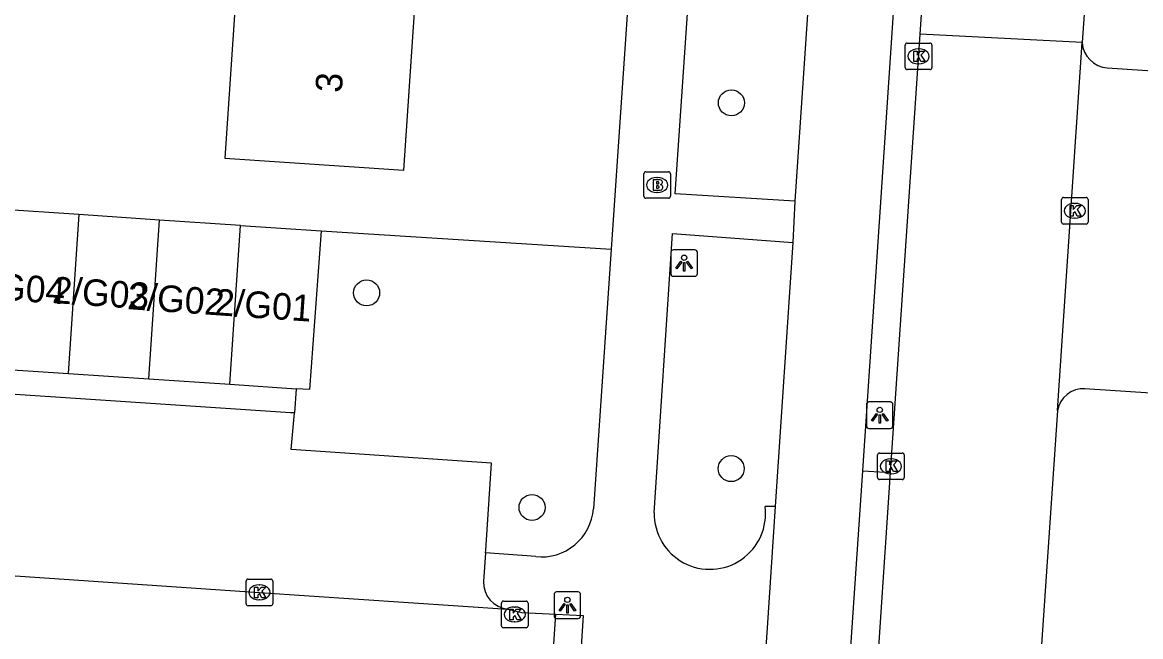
# Model space of a CAD drawing. Extents: x 161848 to 162726, y 385382 to 386521.
# Drawn here: x 161976.28 to 162018.35, y 385610.51 to 385633.63 of the extents above; entities that cross this region are included whole.
import ezdxf

# ---------------------------------------------------------------- set-up
doc = ezdxf.new("R2010")
doc.units = 0
for name, color, linetype in [('IMGEO_Boom', 7, 'Continuous'), ('IMGEO_Brandkraan', 7, 'Continuous'), ('IMGEO_Fietspad_gesloten', 7, 'Continuous'), ('IMGEO_Groenvoorziening', 7, 'Continuous'), ('IMGEO_Kolk', 7, 'Continuous'), ('IMGEO_Lichtpunt', 7, 'Continuous'), ('IMGEO_Pand', 7, 'Continuous'), ('IMGEO_Pand_nummerreeks', 7, 'Continuous'), ('IMGEO_Parkeervlak_open', 7, 'Continuous'), ('IMGEO_Rijbaan_lokaal_open', 7, 'Continuous'), ('IMGEO_Voetpad_open', 7, 'Continuous')]:
    doc.layers.add(name, color=color, linetype=linetype)

msp = doc.modelspace()

# ---------------------------------------------------------------- linework, layer by layer
at = {"layer": 'IMGEO_Boom'}
for centre in [(162002.953, 385630.598), (161989.23, 385623.445), (162002.946, 385616.832), (161995.453, 385615.371)]:
    msp.add_circle(centre, 0.489, dxfattribs=at)
at = {"layer": 'IMGEO_Brandkraan'}
for p, q in [((161999.659, 385627.081), (161999.659, 385627.933)), ((161999.734, 385628.007), (162000.586, 385628.007)), ((162000.66, 385627.933), (162000.66, 385627.081)), ((162000.147, 385627.787), (162000.172, 385627.787)), ((162000.586, 385627.007), (161999.734, 385627.007)), ((162000.17, 385627.227), (162000.145, 385627.227))]:
    msp.add_line(p, q, dxfattribs=at)
for points in [[(161999.659, 385627.081), (161999.659, 385627.933)], [(161999.734, 385628.007), (162000.586, 385628.007)], [(162000.66, 385627.933), (162000.66, 385627.081)], [(162000.007, 385627.707), (162000.007, 385627.307), (162000.22, 385627.307)], [(162000.238, 385627.707), (162000.007, 385627.707)], [(162000.186, 385627.626), (162000.132, 385627.626), (162000.132, 385627.55)], [(162000.132, 385627.55), (162000.185, 385627.55)], [(162000.194, 385627.474), (162000.132, 385627.474), (162000.132, 385627.393)], [(162000.132, 385627.393), (162000.194, 385627.393)], [(162000.586, 385627.007), (161999.734, 385627.007)]]:
    msp.add_lwpolyline(points, dxfattribs=at)
for centre, radius, start, end in [((161999.736, 385627.931), 0.0765, 91.552, 178.448), ((161999.736, 385627.931), 0.0765, 91.552, 178.448), ((162000.584, 385627.931), 0.0765, 1.552, 88.448), ((162000.584, 385627.931), 0.0765, 1.552, 88.448), ((162000.187, 385627.588), 0.0379, 267.8285, 90.9355), ((162000.195, 385627.433), 0.0404, 269.8759, 90.5077), ((162000.242, 385627.562), 0.145, 59.4692, 91.5367), ((162000.267, 385627.609), 0.0922, 285.5137, 58.1501), ((162000.272, 385627.417), 0.105, 301.3115, 78.989), ((161999.736, 385627.083), 0.0765, 181.552, 268.448), ((161999.736, 385627.083), 0.0765, 181.552, 268.448), ((162000.226, 385627.558), 0.251, 268.6676, 293.5347), ((162000.584, 385627.083), 0.0765, 271.552, 358.448), ((162000.584, 385627.083), 0.0765, 271.552, 358.448)]:
    msp.add_arc(centre, radius, start, end, dxfattribs=at)
for centre, major_axis, ratio, start_param, end_param in [((162000.146, 385627.507), (-0.387, 0.002), 0.722429, 4.712389, 7.853982), ((162000.171, 385627.507), (-0.39, 0.002), 0.717154, 1.570796, 4.712389)]:
    msp.add_ellipse(centre, major_axis=major_axis, ratio=ratio, start_param=start_param, end_param=end_param, dxfattribs=at)
at = {"layer": 'IMGEO_Fietspad_gesloten'}
for points in [[(162007.893, 385616.747), (162013.268, 385696.929)], [(162006.478, 385643.76), (162005.344, 385626.899)], [(162005.344, 385626.899), (162005.265, 385625.346)], [(162005.265, 385625.346), (162004.604, 385615.402)], [(162007.138, 385605.527), (162007.893, 385616.747)], [(162004.604, 385615.402), (162004.294, 385610.839), (162003.948, 385605.742)]]:
    msp.add_lwpolyline(points, dxfattribs=at)
at = {"layer": 'IMGEO_Groenvoorziening'}
msp.add_lwpolyline([(161987.519, 385625.781), (161998.429, 385625.093)], dxfattribs=at)
at = {"layer": 'IMGEO_Kolk'}
for p, q in [((162009.493, 385631.924), (162009.493, 385632.776)), ((162009.568, 385632.85), (162010.42, 385632.85)), ((162009.981, 385632.63), (162010.006, 385632.63)), ((162010.494, 385632.776), (162010.494, 385631.924)), ((162010.004, 385632.07), (162009.979, 385632.07)), ((162010.42, 385631.85), (162009.568, 385631.85)), ((162015.372, 385626.111), (162015.372, 385626.963)), ((162015.447, 385627.037), (162016.299, 385627.037)), ((162016.373, 385626.963), (162016.373, 385626.111)), ((162015.86, 385626.817), (162015.885, 385626.817)), ((162015.883, 385626.257), (162015.858, 385626.257)), ((162016.299, 385626.037), (162015.447, 385626.037)), ((162008.455, 385616.494), (162008.455, 385617.346)), ((162008.53, 385617.42), (162009.382, 385617.42)), ((162009.456, 385617.346), (162009.456, 385616.494)), ((162008.943, 385617.2), (162008.968, 385617.2)), ((162008.966, 385616.64), (162008.941, 385616.64)), ((162009.382, 385616.42), (162008.53, 385616.42)), ((161984.771, 385612.674), (161985.623, 385612.674)), ((161984.696, 385611.748), (161984.696, 385612.6)), ((161985.184, 385612.454), (161985.209, 385612.454)), ((161985.697, 385612.6), (161985.697, 385611.748)), ((161985.207, 385611.894), (161985.182, 385611.894)), ((161994.376, 385611.844), (161995.228, 385611.844)), ((161985.623, 385611.674), (161984.771, 385611.674)), ((161994.301, 385610.918), (161994.301, 385611.77)), ((161994.789, 385611.624), (161994.814, 385611.624)), ((161995.302, 385611.77), (161995.302, 385610.918)), ((161994.812, 385611.064), (161994.787, 385611.064)), ((161995.228, 385610.844), (161994.376, 385610.844))]:
    msp.add_line(p, q, dxfattribs=at)
for points in [[(162009.493, 385631.924), (162009.493, 385632.776)], [(162009.568, 385632.85), (162010.42, 385632.85)], [(162009.814, 385632.55), (162009.937, 385632.55), (162009.937, 385632.399), (162010.067, 385632.55), (162010.231, 385632.55), (162010.085, 385632.399), (162010.238, 385632.15), (162010.086, 385632.15), (162010.001, 385632.314), (162009.937, 385632.247), (162009.937, 385632.15), (162009.814, 385632.15), (162009.814, 385632.55)], [(162010.494, 385632.776), (162010.494, 385631.924)], [(162010.42, 385631.85), (162009.568, 385631.85)], [(162015.372, 385626.111), (162015.372, 385626.963)], [(162015.447, 385627.037), (162016.299, 385627.037)], [(162016.373, 385626.963), (162016.373, 385626.111)], [(162015.693, 385626.737), (162015.816, 385626.737), (162015.816, 385626.586), (162015.946, 385626.737), (162016.11, 385626.737), (162015.964, 385626.586), (162016.117, 385626.337), (162015.965, 385626.337), (162015.88, 385626.501), (162015.816, 385626.434), (162015.816, 385626.337), (162015.693, 385626.337), (162015.693, 385626.737)], [(162016.299, 385626.037), (162015.447, 385626.037)], [(162008.455, 385616.494), (162008.455, 385617.346)], [(162008.53, 385617.42), (162009.382, 385617.42)], [(162009.456, 385617.346), (162009.456, 385616.494)], [(162008.776, 385617.12), (162008.899, 385617.12), (162008.899, 385616.969), (162009.029, 385617.12), (162009.193, 385617.12), (162009.047, 385616.969), (162009.2, 385616.72), (162009.048, 385616.72), (162008.963, 385616.884), (162008.899, 385616.817), (162008.899, 385616.72), (162008.776, 385616.72), (162008.776, 385617.12)], [(162009.382, 385616.42), (162008.53, 385616.42)], [(161984.771, 385612.674), (161985.623, 385612.674)], [(161984.696, 385611.748), (161984.696, 385612.6)], [(161985.017, 385612.374), (161985.14, 385612.374), (161985.14, 385612.223), (161985.27, 385612.374), (161985.434, 385612.374), (161985.288, 385612.223), (161985.441, 385611.974), (161985.289, 385611.974), (161985.204, 385612.138), (161985.14, 385612.071), (161985.14, 385611.974), (161985.017, 385611.974), (161985.017, 385612.374)], [(161985.697, 385612.6), (161985.697, 385611.748)], [(161994.376, 385611.844), (161995.228, 385611.844)], [(161985.623, 385611.674), (161984.771, 385611.674)], [(161994.301, 385610.918), (161994.301, 385611.77)], [(161994.622, 385611.544), (161994.745, 385611.544), (161994.745, 385611.393), (161994.875, 385611.544), (161995.039, 385611.544), (161994.893, 385611.393), (161995.046, 385611.144), (161994.894, 385611.144), (161994.809, 385611.308), (161994.745, 385611.241), (161994.745, 385611.144), (161994.622, 385611.144), (161994.622, 385611.544)], [(161995.302, 385611.77), (161995.302, 385610.918)], [(161995.228, 385610.844), (161994.376, 385610.844)]]:
    msp.add_lwpolyline(points, dxfattribs=at)
for centre, start, end in [((162009.57, 385632.774), 91.552, 178.448), ((162009.57, 385632.774), 91.552, 178.448), ((162010.418, 385632.774), 1.552, 88.448), ((162010.418, 385632.774), 1.552, 88.448), ((162009.57, 385631.926), 181.552, 268.448), ((162009.57, 385631.926), 181.552, 268.448), ((162010.418, 385631.926), 271.552, 358.448), ((162010.418, 385631.926), 271.552, 358.448), ((162015.449, 385626.961), 91.552, 178.448), ((162015.449, 385626.961), 91.552, 178.448), ((162016.297, 385626.961), 1.552, 88.448), ((162016.297, 385626.961), 1.552, 88.448), ((162015.449, 385626.113), 181.552, 268.448), ((162015.449, 385626.113), 181.552, 268.448), ((162016.297, 385626.113), 271.552, 358.448), ((162016.297, 385626.113), 271.552, 358.448), ((162008.532, 385617.344), 91.552, 178.448), ((162008.532, 385617.344), 91.552, 178.448), ((162009.38, 385617.344), 1.552, 88.448), ((162009.38, 385617.344), 1.552, 88.448), ((162008.532, 385616.496), 181.552, 268.448), ((162008.532, 385616.496), 181.552, 268.448), ((162009.38, 385616.496), 271.552, 358.448), ((162009.38, 385616.496), 271.552, 358.448), ((161984.773, 385612.598), 91.552, 178.448), ((161984.773, 385612.598), 91.552, 178.448), ((161985.621, 385612.598), 1.552, 88.448), ((161985.621, 385612.598), 1.552, 88.448), ((161994.378, 385611.768), 91.552, 178.448), ((161994.378, 385611.768), 91.552, 178.448), ((161995.226, 385611.768), 1.552, 88.448), ((161995.226, 385611.768), 1.552, 88.448), ((161984.773, 385611.75), 181.552, 268.448), ((161984.773, 385611.75), 181.552, 268.448), ((161985.621, 385611.75), 271.552, 358.448), ((161985.621, 385611.75), 271.552, 358.448), ((161994.378, 385610.92), 181.552, 268.448), ((161994.378, 385610.92), 181.552, 268.448), ((161995.226, 385610.92), 271.552, 358.448), ((161995.226, 385610.92), 271.552, 358.448)]:
    msp.add_arc(centre, 0.0765, start, end, dxfattribs=at)
for centre, major_axis, ratio, start_param, end_param in [((162009.98, 385632.35), (-0.387, 0.002), 0.722429, 4.712389, 7.853982), ((162010.005, 385632.35), (-0.39, 0.002), 0.717154, 1.570796, 4.712389), ((162015.859, 385626.537), (-0.387, 0.002), 0.722429, 4.712389, 7.853982), ((162015.884, 385626.537), (-0.39, 0.002), 0.717154, 1.570796, 4.712389), ((162008.942, 385616.92), (-0.387, 0.002), 0.722429, 4.712389, 7.853982), ((162008.967, 385616.92), (-0.39, 0.002), 0.717154, 1.570796, 4.712389), ((161985.183, 385612.174), (-0.387, 0.002), 0.722429, 4.712389, 7.853982), ((161985.208, 385612.174), (-0.39, 0.002), 0.717154, 1.570796, 4.712389), ((161994.788, 385611.344), (-0.387, 0.002), 0.722429, 4.712389, 7.853982), ((161994.813, 385611.344), (-0.39, 0.002), 0.717154, 1.570796, 4.712389)]:
    msp.add_ellipse(centre, major_axis=major_axis, ratio=ratio, start_param=start_param, end_param=end_param, dxfattribs=at)
at = {"layer": 'IMGEO_Lichtpunt'}
for p, q in [((162000.677, 385624.973), (162000.677, 385624.166)), ((162000.677, 385624.973), (162000.677, 385624.166)), ((162001.579, 385625.068), (162000.771, 385625.068)), ((162001.579, 385625.068), (162000.771, 385625.068)), ((162001.673, 385624.166), (162001.673, 385624.973)), ((162001.673, 385624.166), (162001.673, 385624.973)), ((162000.771, 385624.072), (162001.579, 385624.072)), ((162000.771, 385624.072), (162001.579, 385624.072)), ((162008.035, 385619.245), (162008.035, 385618.438)), ((162008.035, 385619.245), (162008.035, 385618.438)), ((162008.937, 385619.34), (162008.129, 385619.34)), ((162008.937, 385619.34), (162008.129, 385619.34)), ((162009.031, 385618.438), (162009.031, 385619.245)), ((162009.031, 385618.438), (162009.031, 385619.245)), ((162008.129, 385618.344), (162008.937, 385618.344)), ((162008.129, 385618.344), (162008.937, 385618.344)), ((161996.284, 385612.096), (161996.284, 385611.289)), ((161996.284, 385612.096), (161996.284, 385611.289)), ((161997.186, 385612.191), (161996.378, 385612.191)), ((161997.186, 385612.191), (161996.378, 385612.191)), ((161997.28, 385611.289), (161997.28, 385612.096)), ((161997.28, 385611.289), (161997.28, 385612.096)), ((161996.378, 385611.195), (161997.186, 385611.195)), ((161996.378, 385611.195), (161997.186, 385611.195))]:
    msp.add_line(p, q, dxfattribs=at)
for points in [[(162001.051, 385624.637), (162001.09, 385624.609), (162000.902, 385624.347), (162000.864, 385624.374), (162001.051, 385624.637)], [(162001.153, 385624.589), (162001.2, 385624.589), (162001.2, 385624.267), (162001.153, 385624.267), (162001.153, 385624.589)], [(162001.263, 385624.609), (162001.301, 385624.636), (162001.488, 385624.374), (162001.449, 385624.346), (162001.263, 385624.609)], [(162008.409, 385618.909), (162008.448, 385618.881), (162008.26, 385618.619), (162008.222, 385618.646), (162008.409, 385618.909)], [(162008.511, 385618.861), (162008.558, 385618.861), (162008.558, 385618.539), (162008.511, 385618.539), (162008.511, 385618.861)], [(162008.621, 385618.881), (162008.659, 385618.908), (162008.846, 385618.646), (162008.807, 385618.618), (162008.621, 385618.881)], [(161996.658, 385611.76), (161996.697, 385611.732), (161996.509, 385611.47), (161996.471, 385611.497), (161996.658, 385611.76)], [(161996.76, 385611.712), (161996.807, 385611.712), (161996.807, 385611.39), (161996.76, 385611.39), (161996.76, 385611.712)], [(161996.87, 385611.732), (161996.908, 385611.759), (161997.095, 385611.497), (161997.056, 385611.469), (161996.87, 385611.732)]]:
    msp.add_lwpolyline(points, dxfattribs=at)
for centre in [(162001.176, 385624.771), (162008.534, 385619.043), (161996.783, 385611.894)]:
    msp.add_circle(centre, 0.0994, dxfattribs=at)
for centre, start, end in [((162000.771, 385624.973), 90, 180), ((162000.771, 385624.973), 90, 180), ((162001.579, 385624.973), 0, 90), ((162001.579, 385624.973), 0, 90), ((162000.771, 385624.166), 180, 270), ((162000.771, 385624.166), 180, 270), ((162001.579, 385624.166), 270, 0), ((162001.579, 385624.166), 270, 360), ((162008.129, 385619.245), 90, 180), ((162008.129, 385619.245), 90, 180), ((162008.937, 385619.245), 0, 90), ((162008.937, 385619.245), 0, 90), ((162008.129, 385618.438), 180, 270), ((162008.129, 385618.438), 180, 270), ((162008.937, 385618.438), 270, 0), ((162008.937, 385618.438), 270, 360), ((161996.378, 385612.096), 90, 180), ((161996.378, 385612.096), 90, 180), ((161997.186, 385612.096), 0, 90), ((161997.186, 385612.096), 0, 90), ((161996.378, 385611.289), 180, 270), ((161996.378, 385611.289), 180, 270), ((161997.186, 385611.289), 270, 0), ((161997.186, 385611.289), 270, 360)]:
    msp.add_arc(centre, 0.0946, start, end, dxfattribs=at)
at = {"layer": 'IMGEO_Pand'}
for points in [[(161984.292, 385634.466), (161983.891, 385628.515), (161990.625, 385628.06), (161991.027, 385634.016)], [(161978.405, 385626.392), (161975.367, 385626.596)], [(161978.405, 385626.392), (161978.004, 385620.415)], [(161981.443, 385626.189), (161978.405, 385626.392)], [(161981.042, 385620.211), (161981.443, 385626.189)], [(161984.481, 385625.985), (161981.443, 385626.189)], [(161984.08, 385620.007), (161984.481, 385625.985)], [(161984.481, 385625.985), (161987.519, 385625.781)], [(161987.519, 385625.781), (161987.081, 385619.806), (161986.585, 385619.839)], [(161974.966, 385620.619), (161978.004, 385620.415)], [(161978.004, 385620.415), (161981.042, 385620.211)], [(161981.042, 385620.211), (161984.08, 385620.007)], [(161984.08, 385620.007), (161986.585, 385619.839)]]:
    msp.add_lwpolyline(points, dxfattribs=at)
at = {"layer": 'IMGEO_Parkeervlak_open'}
msp.add_lwpolyline([(161993.701, 385613.657), (161993.709, 385613.769), (161993.932, 385617.041), (161986.398, 385617.549), (161986.511, 385618.928)], dxfattribs=at)
at = {"layer": 'IMGEO_Rijbaan_lokaal_open'}
for points in [[(162010.05, 385633.182), (162011.334, 385651.941)], [(162016.295, 385635.013), (162016.148, 385632.865)], [(162008.94, 385616.682), (162010.05, 385633.182)], [(162016.148, 385632.865), (162010.05, 385633.182)], [(162015.218, 385619.015), (162016.148, 385632.865)], [(162015.218, 385619.015), (162014.09, 385602.491)], [(162007.797, 385599.605), (162008.94, 385616.682)], [(161947.158, 385614.769), (161985.197, 385612.173), (161994.548, 385611.545)], [(161994.548, 385611.545), (161995.075, 385611.421), (161996.35, 385611.357)], [(161996.016, 385606.302), (161996.35, 385611.357)], [(161996.35, 385611.357), (161997.378, 385611.304), (161997.056, 385606.216)]]:
    msp.add_lwpolyline(points, dxfattribs=at)
at = {"layer": 'IMGEO_Voetpad_open'}
for points in [[(162003.492, 385700.232), (162000.908, 385661.369), (162001.053, 385661.34), (162000.699, 385656.226), (162000.549, 385656.175), (161998.429, 385625.093)], [(162005.344, 385626.899), (162000.837, 385627.179), (162001.996, 385644.061), (162006.478, 385643.76)], [(162017.093, 385631.914), (162021.069, 385631.652), (162020.267, 385619.569), (162016.256, 385619.841)], [(162000.049, 385615.172), (162000.737, 385625.677), (162005.265, 385625.346)], [(161998.429, 385625.093), (161997.763, 385615.324)], [(161986.511, 385618.928), (161986.369, 385618.938), (161949.651, 385621.38)], [(161986.585, 385619.839), (161986.511, 385618.928)], [(162007.893, 385616.747), (162008.94, 385616.682)], [(162004.604, 385615.402), (162004.222, 385615.406)], [(161993.701, 385613.657), (161993.629, 385612.588)], [(161995.595, 385613.52), (161993.701, 385613.657)]]:
    msp.add_lwpolyline(points, dxfattribs=at)
for centre, radius, start, end in [((162017.177, 385632.942), 1.032, 184.2906, 265.3468), ((162016.202, 385618.843), 0.999, 86.9182, 170.1046), ((161995.802, 385615.476), 1.967, 263.9595, 355.5684), ((162002.144, 385615.138), 2.095, 179.0695, 7.3495), ((161994.629, 385612.543), 1.001, 177.419, 265.3484)]:
    msp.add_arc(centre, radius, start, end, dxfattribs=at)

# ---------------------------------------------------------------- texts
at = {"layer": 'IMGEO_Pand_nummerreeks'}
for s, rotation, p in [('3', 86.138, (161988.295, 385630.962)), ('2/G04', 356.0818, (161974.226, 385623.266)), ('2/G03', 356.0818, (161977.383, 385623.067)), ('2/G02', 356.0818, (161980.208, 385622.837)), ('2/G01', 356.0818, (161983.492, 385622.612))]:
    msp.add_text(s, height=1, rotation=rotation, dxfattribs=at).set_placement(p)

doc.saveas('drawing.dxf')
